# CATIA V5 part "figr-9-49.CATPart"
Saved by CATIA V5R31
Part number: Part1
Bounding box of the stored display mesh (mm): x -53.48 to 62.241, y -50 to 50, z -57.709 to 133.109
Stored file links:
  D:\PROJECTS\Project 2021\US EDITION\CATIA V5 6R 2021\Resources\Part Files\c09_catia_v5_6r2021_prt\c09_catia_v5_6r2021_prt\figr-9-49.CATPart
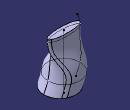
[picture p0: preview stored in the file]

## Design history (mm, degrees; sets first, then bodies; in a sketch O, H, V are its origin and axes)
Body1 (main body)
  Plane1: type Offset, RefPlane xy-plane, Offset 103
  Sketch1 on Plane1, origin (0, 0, 103), H (1, 0, 0), V (0, 1, 0)
    ellipse A1 centre (0, 0) semi-axes 50, 13.2069 rotation 0
    point P1 (50, 0)
    "Radius" A1 = 50
    coincidence: P1 H, A1 P1
  Extremum1: Reference Sketch1, Direction (1, 2, 3)
  Sketch2 on xy-plane, origin (0, 0, 0), H (1, 0, 0), V (0, 1, 0)
    circle A1 centre (0, 0) radius 50
    radius A1 = 50
  Extremum2: Reference Sketch2, Direction (1, 2, 3)
  Sketch3 on zx-plane, origin (0, 0, 0), H (-1, 0, 0), V (0, 0, 1)
    spline S1 through (37.7591, -31.0289) (41.8235, -21.251) (50, 0) (49.8084, 85.7657) (50, 103) (41.6255, 133.1089)
    reference projected line E1 (-50, 103) -> (50, 103) from Sketch1.A1
    point P1 (50, 0)
    point P2 (50, 103)
    distance V P1 = 50
    distance P2 V = 50
    coincidence: P1 H, P2 E1
  Sketch4 on zx-plane, origin (0, 0, 0), H (-1, 0, 0), V (0, 0, 1)
    line L1 (0, 111.062) -> (0, -57.7094)
    point P1 (0, 111.062)
    coincidence: P1 V
    vertical: L1 V
  Loft1: solid, Sections (Sketch1; Sketch2), Spine Sketch4, Guides Sketch3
